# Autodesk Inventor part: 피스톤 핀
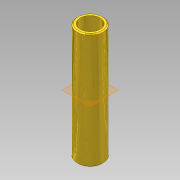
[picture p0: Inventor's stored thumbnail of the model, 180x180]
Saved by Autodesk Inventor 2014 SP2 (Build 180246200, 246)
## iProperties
Manager: KYOUNG IL JANG
Company: 한국ATC센터
Created: 2012-10
Part Number: 피스톤 핀
Document SubType Name: Modeling
Density: 1 g/cm^3
Checked By: KYOUNG IL JANG
Vendor: CBT Solutions
Designer: KYOUNG IL JANG
Material: 일반
Appearance: _시험_금속성 금색
Author: KYOUNG IL JANG
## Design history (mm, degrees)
sketch "스케치1"
  geometry: C1 r 6.5 at (0, 0); C2 r 5 at (0, 0); 1 further point
  constraints: 2 centre point, 2 coincident
  dimensions: "d0" = 13 diameter of C1; "d1" = 1.5 radial gap between concentric circles of C1 C2
extrude "돌출1" new body sketch "스케치1" stored distance "d2" = 58; taper "d3" = 0 deg
chamfer "모따기1" distance "d4" = 0.5; stored, may be unused: second distance "d5" = 2, angle "d6" = 45 deg
node "솔리드1"
